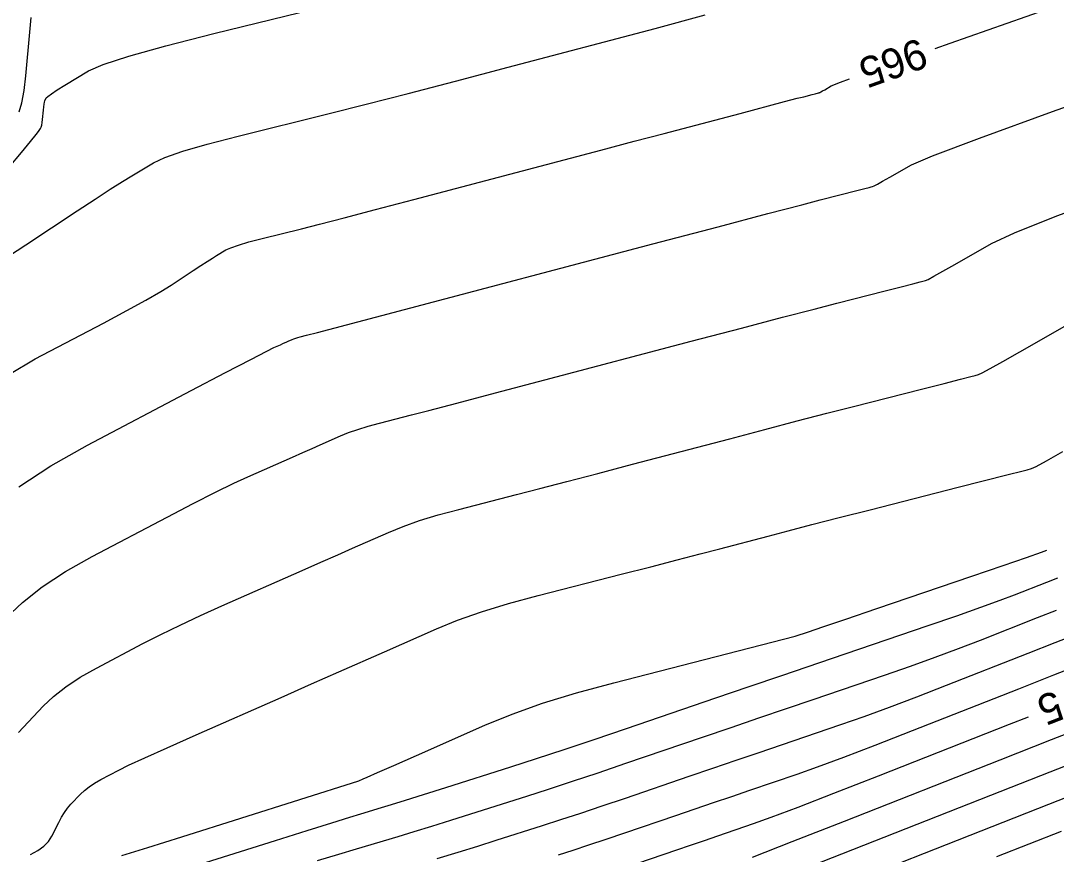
# Model space of a CAD drawing. Extents: x 2175772 to 2185556, y 721391 to 722853.
# Drawn here: x 2178754 to 2178849.6, y 721892.9 to 721969.8 of the extents above; entities that cross this region are included whole.
import ezdxf

# ---------------------------------------------------------------- set-up
doc = ezdxf.new("R2010")
doc.units = 0
doc.layers.add('DT_X_Contour_Major', color=7, linetype='Continuous')
doc.layers.add('DT_X_Contour_Minor', color=7, linetype='Continuous')

msp = doc.modelspace()

# ---------------------------------------------------------------- linework, layer by layer
at = {"layer": 'DT_X_Contour_Major'}
for points in [[(2178838.429, 721967.296), (2178839.814, 721967.785), (2178853.834, 721972.721), (2178859.192, 721974.616), (2178864.749, 721976.601), (2178870.506, 721978.674), (2178876.462, 721980.836), (2178892.613, 721986.719), (2178898.016, 721988.681), (2178902.11, 721990.154), (2178904.895, 721991.137), (2178906.372, 721991.632), (2178908.566, 721992.3), (2178909.926, 721992.723), (2178912.361, 721993.491), (2178915.87, 721994.605), (2178920.453, 721996.065), (2178932.903, 722000.033)], [(2178752.981, 721937.211), (2178755.353, 721938.625), (2178761.659, 721941.942), (2178763.823, 721943.093), (2178765.587, 721944.06), (2178766.949, 721944.842), (2178767.911, 721945.439), (2178769.942, 721946.784), (2178770.648, 721947.25), (2178771.245, 721947.637), (2178771.731, 721947.946), (2178772.107, 721948.177), (2178772.963, 721948.688), (2178773.413, 721948.898), (2178774.122, 721949.144), (2178775.089, 721949.427), (2178776.315, 721949.746), (2178779.928, 721950.644), (2178781.592, 721951.066), (2178783.875, 721951.656), (2178786.777, 721952.414), (2178790.298, 721953.341), (2178804.19, 721957.01), (2178807.57, 721957.902), (2178810.65, 721958.715), (2178813.429, 721959.448), (2178820.441, 721961.298), (2178824.534, 721962.377), (2178825.706, 721962.684), (2178826.296, 721962.837), (2178827.091, 721963.04), (2178827.353, 721963.107), (2178827.666, 721963.187), (2178827.717, 721963.199), (2178827.757, 721963.21), (2178827.798, 721963.229), (2178827.892, 721963.28), (2178828.04, 721963.363), (2178828.24, 721963.477), (2178828.845, 721963.823), (2178829.7, 721964.169), (2178830.519, 721964.469)], [(2178763.358, 721892.791), (2178765.765, 721893.54), (2178768.902, 721894.529), (2178785.242, 721899.699), (2178785.641, 721899.875), (2178786.012, 721900.038), (2178786.953, 721900.453), (2178788.464, 721901.119), (2178790.545, 721902.037), (2178796.854, 721904.819), (2178799.373, 721905.847), (2178802.198, 721906.844), (2178805.33, 721907.809), (2178808.768, 721908.744), (2178825.525, 721913.032), (2178826.748, 721913.45), (2178828.07, 721913.9), (2178830.174, 721914.618), (2178833.062, 721915.604), (2178841.807, 721918.587), (2178844.709, 721919.579), (2178846.859, 721920.318), (2178848.256, 721920.803), (2178848.753, 721920.982)], [(2178809.715, 721891.667), (2178814.572, 721893.323), (2178815.863, 721893.764), (2178817.131, 721894.197), (2178818.375, 721894.621), (2178821.661, 721895.742), (2178823.306, 721896.333), (2178825.776, 721897.265), (2178829.073, 721898.539), (2178833.195, 721900.154), (2178845.288, 721904.916), (2178847.047, 721905.608)]]:
    msp.add_lwpolyline(points, dxfattribs=at)
at = {"layer": 'DT_X_Contour_Minor'}
for points in [[(2178752.969, 721956.323), (2178754.1, 721957.696), (2178754.928, 721958.706), (2178755.451, 721959.351), (2178755.671, 721959.633), (2178755.853, 721959.898), (2178755.916, 721960.026), (2178755.969, 721960.209), (2178756.012, 721960.447), (2178756.046, 721960.742), (2178756.122, 721961.6), (2178756.152, 721961.895), (2178756.186, 721962.134), (2178756.223, 721962.318), (2178756.264, 721962.447), (2178756.378, 721962.717), (2178756.518, 721962.866), (2178756.853, 721963.113), (2178757.382, 721963.458), (2178758.106, 721963.9), (2178760.295, 721965.207), (2178761.634, 721965.791), (2178764.006, 721966.56), (2178767.413, 721967.514), (2178771.855, 721968.655), (2178785.077, 721971.943)], [(2178752.903, 721948.11), (2178754.506, 721949.166), (2178759.237, 721952.301), (2178760.883, 721953.385), (2178762.272, 721954.288), (2178763.405, 721955.008), (2178764.281, 721955.545), (2178766.275, 721956.737), (2178767.324, 721957.226), (2178768.976, 721957.799), (2178771.229, 721958.457), (2178774.085, 721959.2), (2178782.503, 721961.294), (2178785.902, 721962.149), (2178789.786, 721963.144), (2178794.155, 721964.28), (2178799.008, 721965.556), (2178812.598, 721969.144), (2178817.217, 721970.383)], [(2178753.893, 721961.426), (2178754.142, 721962.282), (2178754.345, 721963.398), (2178754.501, 721964.774), (2178754.856, 721968.789), (2178754.991, 721970.15)], [(2178753.86, 721926.818), (2178756.816, 721928.763), (2178760.195, 721930.67), (2178769.768, 721935.705), (2178772.937, 721937.37), (2178775.265, 721938.587), (2178776.752, 721939.358), (2178777.397, 721939.68), (2178777.998, 721939.945), (2178778.212, 721940.04), (2178778.576, 721940.2), (2178778.725, 721940.266), (2178779.093, 721940.428), (2178779.241, 721940.489), (2178779.41, 721940.548), (2178779.599, 721940.606), (2178779.809, 721940.663), (2178780.395, 721940.812), (2178781.431, 721941.084), (2178784.102, 721941.788), (2178788.406, 721942.923), (2178812.357, 721949.242), (2178818.39, 721950.833), (2178822.981, 721952.04), (2178826.128, 721952.865), (2178827.833, 721953.307), (2178831.322, 721954.196), (2178831.955, 721954.357), (2178832.355, 721954.459), (2178832.521, 721954.502), (2178832.652, 721954.535), (2178832.789, 721954.6), (2178833.1, 721954.768), (2178833.586, 721955.041), (2178834.247, 721955.417), (2178836.242, 721956.56), (2178838.188, 721957.39), (2178842.53, 721959.022), (2178849.267, 721961.456), (2178858.401, 721964.692)], [(2178752.654, 721914.698), (2178754.183, 721916.16), (2178756.018, 721917.595), (2178758.159, 721919.003), (2178760.605, 721920.384), (2178767.535, 721924.029), (2178769.951, 721925.288), (2178772, 721926.33), (2178773.683, 721927.155), (2178775, 721927.763), (2178779.101, 721929.572), (2178780.07, 721929.999), (2178780.93, 721930.378), (2178781.68, 721930.709), (2178783.533, 721931.526), (2178784.28, 721931.83), (2178785.129, 721932.127), (2178786.081, 721932.419), (2178787.135, 721932.705), (2178790.084, 721933.46), (2178791.684, 721933.874), (2178794.273, 721934.552), (2178797.85, 721935.492), (2178802.417, 721936.696), (2178815.912, 721940.257), (2178820.548, 721941.478), (2178824.337, 721942.472), (2178827.278, 721943.238), (2178829.37, 721943.777), (2178833.82, 721944.911), (2178835.29, 721945.285), (2178836.365, 721945.559), (2178837.043, 721945.732), (2178837.548, 721945.861), (2178837.78, 721945.97), (2178838.308, 721946.256), (2178839.133, 721946.719), (2178840.254, 721947.358), (2178843.639, 721949.297), (2178845.745, 721950.284), (2178849.522, 721951.789), (2178854.973, 721953.813)], [(2178753.823, 721904.144), (2178756.095, 721906.579), (2178757.041, 721907.484), (2178758.177, 721908.372), (2178759.501, 721909.243), (2178761.015, 721910.098), (2178765.303, 721912.353), (2178766.965, 721913.206), (2178768.736, 721914.072), (2178770.615, 721914.952), (2178772.603, 721915.846), (2178779.99, 721919.103), (2178781.736, 721919.873), (2178783.284, 721920.556), (2178784.635, 721921.151), (2178787.974, 721922.624), (2178789.318, 721923.171), (2178790.848, 721923.707), (2178792.562, 721924.232), (2178794.461, 721924.747), (2178799.773, 721926.107), (2178801.937, 721926.664), (2178804.444, 721927.315), (2178807.295, 721928.062), (2178810.489, 721928.903), (2178819.467, 721931.271), (2178822.707, 721932.123), (2178825.693, 721932.903), (2178828.427, 721933.611), (2178830.907, 721934.247), (2178837.185, 721935.846), (2178839.259, 721936.375), (2178840.775, 721936.761), (2178841.731, 721937.005), (2178842.129, 721937.106), (2178842.443, 721937.186), (2178842.771, 721937.341), (2178843.516, 721937.744), (2178844.679, 721938.397), (2178846.261, 721939.298), (2178851.036, 721942.034)], [(2178754.925, 721892.903), (2178755.61, 721893.269), (2178756.167, 721893.668), (2178756.597, 721894.101), (2178756.899, 721894.568), (2178757.534, 721895.858), (2178757.783, 721896.325), (2178758.055, 721896.758), (2178758.348, 721897.159), (2178758.664, 721897.526), (2178759.536, 721898.461), (2178759.899, 721898.808), (2178760.335, 721899.149), (2178760.844, 721899.483), (2178761.425, 721899.811), (2178763.071, 721900.677), (2178763.98, 721901.124), (2178765.472, 721901.815), (2178767.547, 721902.749), (2178770.205, 721903.928), (2178778.072, 721907.397), (2178780.879, 721908.635), (2178783.401, 721909.747), (2178787.59, 721911.594), (2178792.414, 721913.722), (2178794.356, 721914.512), (2178796.566, 721915.286), (2178799.043, 721916.046), (2178801.788, 721916.79), (2178809.462, 721918.754), (2178812.189, 721919.454), (2178814.615, 721920.079), (2178816.739, 721920.631), (2178818.562, 721921.109), (2178823.022, 721922.286), (2178824.865, 721922.769), (2178827.05, 721923.335), (2178829.576, 721923.984), (2178832.445, 721924.717), (2178840.549, 721926.782), (2178845.184, 721927.963), (2178846.419, 721928.277), (2178846.933, 721928.408), (2178847.339, 721928.511), (2178847.761, 721928.711), (2178848.724, 721929.232), (2178850.226, 721930.074)], [(2178768.931, 721891.463), (2178777.537, 721894.186), (2178780.45, 721895.106), (2178782.735, 721895.824), (2178784.393, 721896.339), (2178785.423, 721896.653), (2178787.333, 721897.219), (2178788.241, 721897.495), (2178789.532, 721897.896), (2178791.207, 721898.423), (2178793.266, 721899.075), (2178799.267, 721900.983), (2178801.622, 721901.742), (2178804.188, 721902.584), (2178806.965, 721903.512), (2178809.952, 721904.525), (2178818.2, 721907.339), (2178821.264, 721908.384), (2178824.274, 721909.411), (2178830.125, 721911.407), (2178837.777, 721914.018), (2178840.429, 721914.93), (2178842.642, 721915.707), (2178844.419, 721916.35), (2178845.758, 721916.859), (2178848.747, 721918.035), (2178849.747, 721918.428)], [(2178781.423, 721892.327), (2178783.395, 721892.933), (2178785.012, 721893.42), (2178788.85, 721894.558), (2178790.351, 721895.008), (2178791.974, 721895.505), (2178793.719, 721896.048), (2178795.587, 721896.638), (2178800.732, 721898.274), (2178802.751, 721898.924), (2178804.951, 721899.647), (2178807.332, 721900.442), (2178809.893, 721901.31), (2178816.964, 721903.723), (2178819.591, 721904.619), (2178822.171, 721905.499), (2178824.703, 721906.363), (2178827.187, 721907.211), (2178833.748, 721909.449), (2178836.148, 721910.281), (2178838.426, 721911.097), (2178840.582, 721911.897), (2178842.617, 721912.683), (2178847.882, 721914.756), (2178849.629, 721915.442)], [(2178792.461, 721892.521), (2178794.415, 721893.113), (2178796.231, 721893.674), (2178797.909, 721894.201), (2178802.197, 721895.565), (2178803.881, 721896.107), (2178805.714, 721896.709), (2178807.699, 721897.372), (2178809.834, 721898.096), (2178815.728, 721900.107), (2178817.918, 721900.854), (2178820.069, 721901.588), (2178822.179, 721902.308), (2178824.25, 721903.014), (2178829.719, 721904.88), (2178831.867, 721905.631), (2178834.209, 721906.486), (2178836.746, 721907.445), (2178839.477, 721908.506), (2178847.018, 721911.476), (2178849.511, 721912.457), (2178851.334, 721913.172)], [(2178803.662, 721892.856), (2178805.01, 721893.289), (2178806.478, 721893.771), (2178808.066, 721894.302), (2178809.775, 721894.881), (2178814.492, 721896.491), (2178817.966, 721897.676), (2178819.655, 721898.252), (2178821.313, 721898.818), (2178825.69, 721900.311), (2178827.586, 721900.982), (2178829.993, 721901.876), (2178832.909, 721902.992), (2178836.336, 721904.33), (2178846.153, 721908.196), (2178849.392, 721909.471), (2178851.747, 721910.395)], [(2178821.56, 721892.655), (2178825.236, 721894.086), (2178830.054, 721895.978), (2178844.424, 721901.636), (2178849.156, 721903.499), (2178852.574, 721904.842)], [(2178826.913, 721891.802), (2178843.559, 721898.356), (2178849.037, 721900.513), (2178852.987, 721902.066)], [(2178823.772, 721887.626), (2178848.919, 721897.527), (2178853.4, 721899.289)], [(2178844.135, 721892.704), (2178850.097, 721895.051)]]:
    msp.add_lwpolyline(points, dxfattribs=at)

# ---------------------------------------------------------------- texts
at = {"layer": 'DT_X_Contour_Major'}
for s, rotation, p in [('965', 199.66694, (2178837.04, 721968.299)), ('975', 201.33606, (2178853.414, 721909.609))]:
    msp.add_text(s, height=2.8, rotation=rotation, dxfattribs=at).set_placement(p)

doc.saveas('drawing.dxf')
